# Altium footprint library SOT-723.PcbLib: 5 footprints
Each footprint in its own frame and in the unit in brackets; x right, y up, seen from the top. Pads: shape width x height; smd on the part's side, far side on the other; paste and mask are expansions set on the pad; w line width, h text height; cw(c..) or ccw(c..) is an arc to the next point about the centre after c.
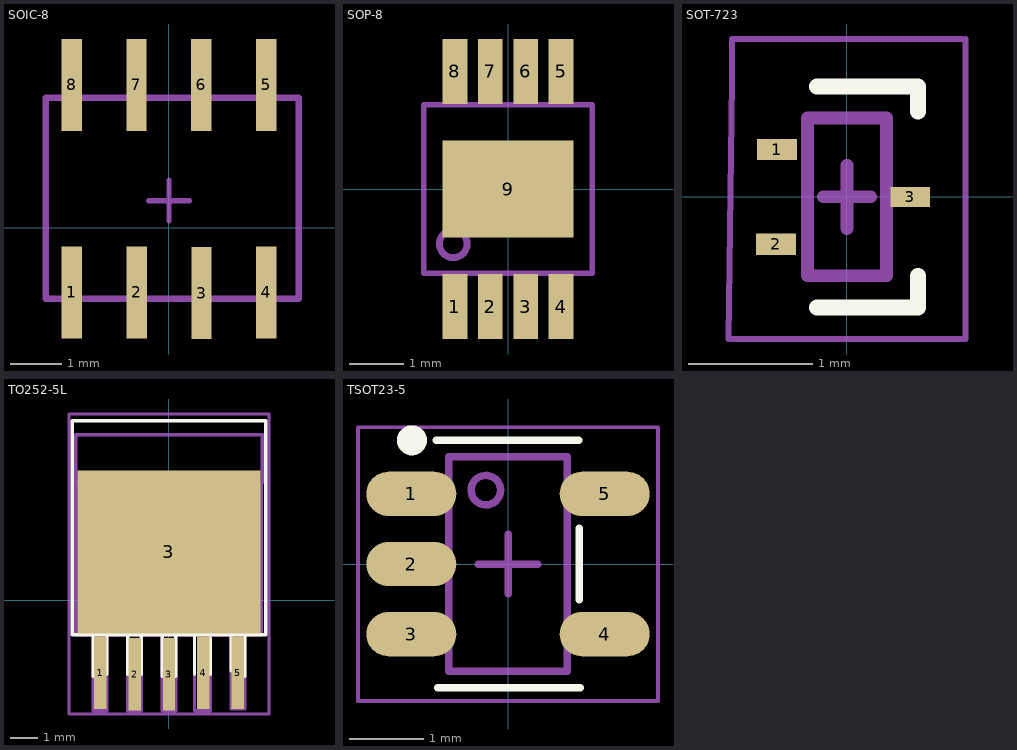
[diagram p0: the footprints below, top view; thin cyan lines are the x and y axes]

## SOIC-8 [mm]
height 0.081
pads (8):
  rect 0.4x1.8 smd: 1(-1.9,-1.27) 2(-0.63,-1.27) 3(0.64,-1.283) 4(1.905,-1.27) 5(1.91,2.795) 6(0.635,2.795) 7(-0.635,2.795) 8(-1.905,2.795)
Mechanical 13:
  lines w0.127: -2.413,-1.397 -2.413,2.54 2.54,2.54 2.54,1.556 2.54,-0.413 2.54,-0.659 2.54,-1.151 2.54,-1.397 -2.413,-1.397
Mechanical 15:
  lines w0.102: -0.4,0.527 0.4,0.527 ; 0,0.127 0,0.927
3D body: height 1, standoff 0, extent -2.1,1.968 -1.7,3.3
3D body: height 1, standoff 0, extent -0.83,1.968 -0.43,3.3
3D body: height 1, standoff 0, extent 0.44,1.968 0.84,3.3
3D body: height 1, standoff 0, extent 1.71,1.968 2.11,3.3
3D body: height 1, standoff 0, extent -2.1,-1.936 -1.7,-0.604
3D body: height 1, standoff 0, extent -0.83,-1.936 -0.43,-0.604
3D body: height 1, standoff 0, extent 0.44,-1.949 0.84,-0.617
3D body: height 1, standoff 0, extent 1.705,-1.935 2.105,-0.604
3D body: height 3.18, standoff 3.17, extent -2.3,-1.4 -1.5,-0.6
3D body: height 3.17, standoff 0, extent -2.54,-1.333 2.54,2.604

## SOP-8 [mil]
pads (9):
  rect 18x47 smd mask+2: 1(-38.4,-85) 2(-12.8,-85) 3(12.8,-85) 4(38.4,-85) 5(38.4,85) 6(12.8,85) 7(-12.8,85) 8(-38.4,85)
  rect 95x70 smd mask+2: 9(0,0)
Mechanical 13:
  lines w4: -61,-61 -61,61 61,61 61,-61 -61,-61
  lines w5: -49.56,-39.69 cw(c-39.56,-39.69) -39.56,-29.69 cw(c-39.56,-39.69) -29.56,-39.69 cw(c-39.56,-39.69) -39.56,-49.69 cw(c-39.56,-39.69) -49.56,-39.69
3D body: height 43.31, standoff 5.91, extent -61,-61 61,61
3D body: height 45.28, standoff 43.31, extent -49.56,-49.69 -29.56,-29.69

## SOT-723 [mm]
height 0.45
pads (3):
  rect 0.32x0.17 smd: 1(-0.563,0.381) 2(-0.571,-0.381)
  rect 0.32x0.16 smd: 3(0.508,0)
Top Overlay:
  lines w0.127: -0.241,-0.889 0.572,-0.889 0.572,-0.635 ; -0.241,0.889 0.572,0.889 0.572,0.686
Mechanical 13:
  lines w0.102: -0.317,-0.635 0.318,-0.635 0.318,0.635 -0.317,0.635 -0.317,-0.635
Mechanical 15:
  lines w0.051: -0.952,-1.143 -0.924,0.927 -0.924,1.27 0.926,1.27 ; -0.928,-1.143 0.953,-1.143 0.953,1.27
  lines w0.102: -0.19,0 0.191,0 ; 0,-0.254 0,0.254
3D body: height 1.02, standoff 0, extent -0.317,-0.635 0.318,0.635
3D body: height 0.3, standoff 0, extent -0.571,-0.495 -0.366,-0.266
3D body: height 0.3, standoff 0, extent 0.318,-0.166 0.63,0.166
3D body: height 0.3, standoff 0, extent 0.8,-0.225 1.275,0.225
3D body: height 0.3, standoff 0, extent -0.563,0.267 -0.358,0.496

## TO252-5L [mm]
height 2.19
pads (6):
  rect 0.46x2.67 smd: 1(-2.54,-2.667) 2(-1.27,-2.73) 3(0,-2.73) 4(1.27,-2.667) 5(2.54,-2.667)
  rect 6.73x6 smd paste-10: 3(0,1.778)
Top Overlay:
  lines w0.127: -2.794,-2.794 -2.794,-1.27 ; -2.286,-2.73 -2.286,-1.27 ; -1.524,-2.73 -1.524,-1.27 ; -1.016,-2.73 -1.016,-1.27 ; -0.254,-2.794 -0.254,-1.27 ; 0.254,-2.794 0.254,-1.27 ; 0.94,-2.73 0.94,-1.27 ; 1.524,-2.73 1.524,-1.397 ; 2.286,-2.603 2.286,-1.27 ; 2.794,-2.794 2.794,-1.27 ; -3.556,-1.27 3.556,-1.27 3.556,6.604 -3.556,6.604 -3.556,-1.27
Top Paste:
  circle w0.9: c2.1,2.9 r0.45
  circle w0.9: c-2.1,2.9 r0.45
  circle w0.9: c0,2.9 r0.45
  circle w0.9: c2.1,0.7 r0.45
  circle w0.9: c-2.1,0.7 r0.45
  circle w0.9: c0,0.7 r0.45
Mechanical 13:
  lines w0.127: -3.429,4.318 3.429,4.318 ; -2.794,-1.27 -2.794,-4.064 -2.286,-4.064 -2.286,-1.27 ; -1.524,-1.397 -1.524,-4.064 -1.016,-4.064 -1.016,-1.397 ; -0.254,-1.397 -0.254,-4.064 0.254,-4.064 0.254,-3.397 0.254,-2.064 0.254,-1.27 ; 0.94,-1.27 0.94,-4.064 1.524,-4.064 1.524,-1.27 ; 2.286,-1.333 2.286,-4 2.794,-4 2.794,-1.333 ; -3.429,-1.27 3.404,-1.27 3.404,2.642 3.404,4.318 3.429,4.343 3.429,6.096 -3.429,6.096 -3.429,2.667 -3.429,-1.27
Mechanical 15:
  lines w0.102: -1.016,0 1.016,0 ; 0,-1.016 0,1.016
  lines w0.127: -3.683,-4.191 -3.683,6.858 3.683,6.858 3.683,-4.191 -3.683,-4.191
3D body: height 0.5, standoff 0, extent 2.286,-4 2.794,-1.333
3D body: height 0.5, standoff 0, extent 1.016,-4.064 1.524,-1.27
3D body: height 0.5, standoff 0, extent -0.254,-4.064 0.254,-1.397
3D body: height 0.5, standoff 0, extent -1.524,-4.064 -1.016,-1.27
3D body: height 0.5, standoff 0, extent -2.794,-4.064 -2.286,-1.27
3D body: height 1, standoff 0, extent -2.337,4.826 2.413,6.096
3D body: height 3.5, standoff 0, extent -3.404,-1.27 3.404,4.826

## TSOT23-5 [mm] "5-LEAD plastic"
height 0.85
pads (5):
  oval 1.22x0.6 smd mask+0.051: 1(-1.31,0.95) 2(-1.31,0) 3(-1.31,-0.95) 4(1.31,-0.95) 5(1.31,0.95)
Top Overlay:
  circle w0.203: c-1.302,1.675 r0.102
  lines w0.102: -0.975,1.675 0.955,1.675 ; -0.95,-1.675 0.98,-1.675 ; 0.965,-0.483 0.965,0.483
Mechanical 13:
  circle w0.1: c-0.3,1 r0.2
  lines w0.102: -0.8,-1.45 -0.8,1.45 0.8,1.45 0.8,-1.45 -0.8,-1.45
Mechanical 15:
  lines w0.051: -2.032,-1.854 -2.032,1.854 2.032,1.854 2.032,-1.854 -2.032,-1.854
  lines w0.102: -0.4,0 0.4,0 ; 0,-0.4 0,0.4
3D body: height 1.46, standoff 1.45, extent -0.5,0.8 -0.1,1.2
3D body: height 1.45, standoff 0, extent -0.8,-1.45 0.8,1.45
3D body: height 0.3, standoff 0, extent -1.275,0.725 -0.8,1.175
3D body: height 0.3, standoff 0, extent -1.288,-1.175 -0.812,-0.725
3D body: height 0.3, standoff 0, extent -1.275,-0.225 -0.8,0.225
3D body: height 0.3, standoff 0, extent 0.812,0.725 1.288,1.175
3D body: height 0.3, standoff 0, extent 0.812,-1.175 1.288,-0.725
